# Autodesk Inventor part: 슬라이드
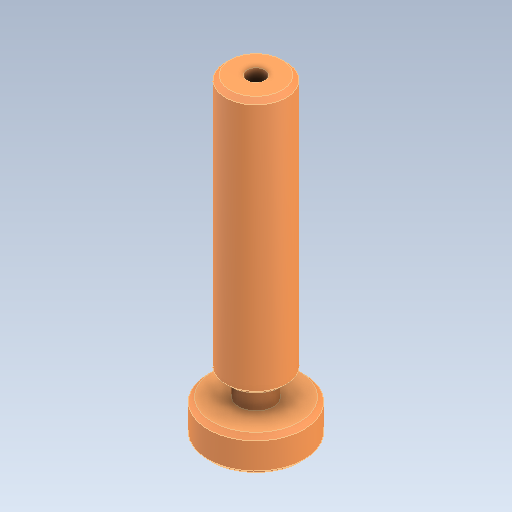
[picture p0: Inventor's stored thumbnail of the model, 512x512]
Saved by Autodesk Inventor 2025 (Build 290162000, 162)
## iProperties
Created: 2024-07
Part Number: 슬라이드
Material: 강철, 연강
Document SubType Name: Modeling
Designer: 미서니
Density: 7.86 g/cm^3
Appearance: 기본값
Author: jhkim
Sending System: Autodesk Inventor 2025
Preprocessor: ST-DEVELOPER v20
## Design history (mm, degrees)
feature "솔리드1"
node "솔리드2"
